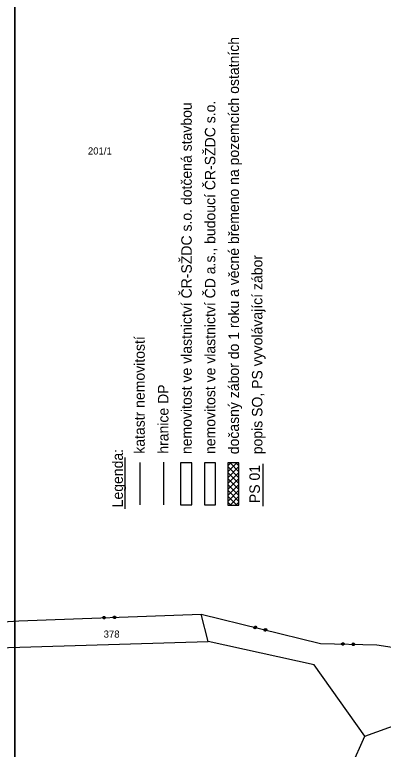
# Model space of a CAD drawing. Extents: x -866656 to -858817, y -1041816 to -1038653.
# Drawn here: x -864286.2 to -864198.3, y -1040985.3 to -1040809.9 of the extents above; entities that cross this region are included whole.
import ezdxf

# ---------------------------------------------------------------- set-up
doc = ezdxf.new("R2010")
doc.units = 0
for name, color, linetype in [('tisk ramy', 7, 'Continuous'), ('Vrstva 1', 7, 'Continuous'), ('Vrstva 3', 7, 'Continuous'), ('Vrstva 53', 7, 'Continuous'), ('Vrstva 7', 7, 'Continuous')]:
    doc.layers.add(name, color=color, linetype=linetype)

msp = doc.modelspace()

# ---------------------------------------------------------------- linework, layer by layer
at = {"layer": 'tisk ramy'}
for points in [[(-864009.22, -1041281.26), (-864009.22, -1040246.26), (-864286.22, -1040246.26), (-864286.22, -1041281.26)], [(-864286.22, -1041281.26), (-864286.22, -1040246.26), (-864009.22, -1040246.26), (-864009.22, -1041281.26)]]:
    msp.add_lwpolyline(points, close=True, dxfattribs=at)
at = {"layer": 'Vrstva 1'}
for p, q in [((-864240.08, -1040959.55), (-864241.77, -1040953.03)), ((-864315.22, -1040961.89), (-864240.08, -1040959.55)), ((-864214.8, -1040965.14), (-864240.08, -1040959.55)), ((-864202.71, -1040982.19), (-864142.49, -1040960.45)), ((-864202.71, -1040982.19), (-864214.8, -1040965.14)), ((-864221.29, -1041022.99), (-864202.71, -1040982.19))]:
    msp.add_line(p, q, dxfattribs=at)
at = {"layer": 'Vrstva 3'}
for p, q in [((-864235.42, -1040919.07), (-864233.28, -1040916.94)), ((-864235.42, -1040917.65), (-864234.7, -1040916.94)), ((-864232.76, -1040920.48), (-864235.42, -1040917.82)), ((-864235.42, -1040920.48), (-864232.76, -1040917.82)), ((-864232.76, -1040919.07), (-864234.89, -1040916.94)), ((-864232.76, -1040917.65), (-864233.47, -1040916.94)), ((-864232.76, -1040921.9), (-864235.42, -1040919.24)), ((-864235.42, -1040921.9), (-864232.76, -1040919.24)), ((-864232.76, -1040923.31), (-864235.42, -1040920.65)), ((-864235.42, -1040923.31), (-864232.76, -1040920.65)), ((-864232.76, -1040924.72), (-864235.42, -1040922.07)), ((-864235.42, -1040924.72), (-864232.76, -1040922.07)), ((-864232.76, -1040926.14), (-864235.42, -1040923.48)), ((-864235.42, -1040926.14), (-864232.76, -1040923.48)), ((-864233.28, -1040927.03), (-864235.42, -1040924.89)), ((-864234.89, -1040927.03), (-864232.76, -1040924.89)), ((-864234.7, -1040927.03), (-864235.42, -1040926.31)), ((-864233.47, -1040927.03), (-864232.76, -1040926.31)), ((-864314.63, -1040956.27), (-864285.28, -1040954.67)), ((-864314.63, -1040956.27), (-864285.28, -1040954.67)), ((-864285.28, -1040954.67), (-864241.77, -1040953.03)), ((-864285.28, -1040954.67), (-864241.77, -1040953.03)), ((-864265.23, -1040953.81), (-864265.04, -1040953.61)), ((-864265.23, -1040953.81), (-864265.04, -1040953.61)), ((-864265.22, -1040954.01), (-864265.23, -1040953.81)), ((-864265.22, -1040954.01), (-864265.23, -1040953.81)), ((-864265.01, -1040954.21), (-864265.22, -1040954.01)), ((-864265.01, -1040954.21), (-864265.22, -1040954.01)), ((-864265.13, -1040953.81), (-864265.12, -1040954.01)), ((-864265.13, -1040953.81), (-864265.12, -1040954.01)), ((-864265.12, -1040954.01), (-864265.02, -1040954.11)), ((-864265.12, -1040954.01), (-864265.02, -1040954.11)), ((-864265.04, -1040953.61), (-864264.83, -1040953.6)), ((-864265.04, -1040953.61), (-864264.83, -1040953.6)), ((-864265.03, -1040953.71), (-864264.83, -1040953.7)), ((-864265.03, -1040953.71), (-864264.83, -1040953.7)), ((-864265.02, -1040954.11), (-864265.03, -1040953.71)), ((-864265.02, -1040954.11), (-864265.03, -1040953.71)), ((-864264.81, -1040954.2), (-864265.01, -1040954.21)), ((-864264.81, -1040954.2), (-864265.01, -1040954.21)), ((-864264.93, -1040953.7), (-864264.92, -1040954.1)), ((-864264.93, -1040953.7), (-864264.92, -1040954.1)), ((-864264.83, -1040953.6), (-864264.63, -1040953.79)), ((-864264.83, -1040953.6), (-864264.63, -1040953.79)), ((-864264.83, -1040953.7), (-864264.82, -1040954.1)), ((-864264.83, -1040953.7), (-864264.82, -1040954.1)), ((-864264.82, -1040954.1), (-864264.72, -1040953.99)), ((-864264.82, -1040954.1), (-864264.72, -1040953.99)), ((-864264.62, -1040953.99), (-864264.81, -1040954.2)), ((-864264.62, -1040953.99), (-864264.81, -1040954.2)), ((-864264.72, -1040953.99), (-864264.73, -1040953.8)), ((-864264.72, -1040953.99), (-864264.73, -1040953.8)), ((-864264.63, -1040953.79), (-864264.62, -1040953.99)), ((-864264.63, -1040953.79), (-864264.62, -1040953.99)), ((-864262.73, -1040953.72), (-864262.54, -1040953.51)), ((-864262.73, -1040953.72), (-864262.54, -1040953.51)), ((-864262.72, -1040953.92), (-864262.73, -1040953.72)), ((-864262.72, -1040953.92), (-864262.73, -1040953.72)), ((-864262.51, -1040954.11), (-864262.72, -1040953.92)), ((-864262.51, -1040954.11), (-864262.72, -1040953.92)), ((-864262.63, -1040953.72), (-864262.62, -1040953.92)), ((-864262.63, -1040953.72), (-864262.62, -1040953.92)), ((-864262.62, -1040953.92), (-864262.52, -1040954.01)), ((-864262.62, -1040953.92), (-864262.52, -1040954.01)), ((-864262.54, -1040953.51), (-864262.34, -1040953.51)), ((-864262.54, -1040953.51), (-864262.34, -1040953.51)), ((-864262.53, -1040953.61), (-864262.33, -1040953.6)), ((-864262.53, -1040953.61), (-864262.33, -1040953.6)), ((-864262.52, -1040954.01), (-864262.53, -1040953.61)), ((-864262.52, -1040954.01), (-864262.53, -1040953.61)), ((-864262.31, -1040954.1), (-864262.51, -1040954.11)), ((-864262.31, -1040954.1), (-864262.51, -1040954.11)), ((-864262.43, -1040953.61), (-864262.42, -1040954.01)), ((-864262.43, -1040953.61), (-864262.42, -1040954.01)), ((-864262.34, -1040953.51), (-864262.13, -1040953.7)), ((-864262.34, -1040953.51), (-864262.13, -1040953.7)), ((-864262.33, -1040953.6), (-864262.32, -1040954)), ((-864262.33, -1040953.6), (-864262.32, -1040954)), ((-864262.32, -1040954), (-864262.22, -1040953.9)), ((-864262.32, -1040954), (-864262.22, -1040953.9)), ((-864262.12, -1040953.9), (-864262.31, -1040954.1)), ((-864262.12, -1040953.9), (-864262.31, -1040954.1)), ((-864262.22, -1040953.9), (-864262.23, -1040953.7)), ((-864262.22, -1040953.9), (-864262.23, -1040953.7)), ((-864262.13, -1040953.7), (-864262.12, -1040953.9)), ((-864262.13, -1040953.7), (-864262.12, -1040953.9)), ((-864241.77, -1040953.03), (-864213.28, -1040960.07)), ((-864241.77, -1040953.03), (-864213.28, -1040960.07)), ((-864229.2, -1040956.24), (-864229.15, -1040956.05)), ((-864229.2, -1040956.24), (-864229.15, -1040956.05)), ((-864229.05, -1040956.48), (-864229.2, -1040956.24)), ((-864229.05, -1040956.48), (-864229.2, -1040956.24)), ((-864229.15, -1040956.05), (-864228.91, -1040955.9)), ((-864229.15, -1040956.05), (-864228.91, -1040955.9)), ((-864229.05, -1040956.07), (-864229.1, -1040956.26)), ((-864229.05, -1040956.07), (-864229.1, -1040956.26)), ((-864229.1, -1040956.26), (-864229.03, -1040956.38)), ((-864229.1, -1040956.26), (-864229.03, -1040956.38)), ((-864228.86, -1040956.53), (-864229.05, -1040956.48)), ((-864228.86, -1040956.53), (-864229.05, -1040956.48)), ((-864229.03, -1040956.38), (-864228.93, -1040956)), ((-864229.03, -1040956.38), (-864228.93, -1040956)), ((-864228.93, -1040956), (-864228.74, -1040956.04)), ((-864228.93, -1040956), (-864228.74, -1040956.04)), ((-864228.84, -1040956.02), (-864228.93, -1040956.41)), ((-864228.84, -1040956.02), (-864228.93, -1040956.41)), ((-864228.91, -1040955.9), (-864228.71, -1040955.95)), ((-864228.91, -1040955.9), (-864228.71, -1040955.95)), ((-864228.62, -1040956.38), (-864228.86, -1040956.53)), ((-864228.62, -1040956.38), (-864228.86, -1040956.53)), ((-864228.74, -1040956.04), (-864228.83, -1040956.43)), ((-864228.74, -1040956.04), (-864228.83, -1040956.43)), ((-864228.83, -1040956.43), (-864228.71, -1040956.36)), ((-864228.83, -1040956.43), (-864228.71, -1040956.36)), ((-864228.71, -1040955.95), (-864228.57, -1040956.19)), ((-864228.71, -1040955.95), (-864228.57, -1040956.19)), ((-864228.71, -1040956.36), (-864228.67, -1040956.17)), ((-864228.71, -1040956.36), (-864228.67, -1040956.17)), ((-864228.57, -1040956.19), (-864228.62, -1040956.38)), ((-864228.57, -1040956.19), (-864228.62, -1040956.38)), ((-864226.72, -1040956.64), (-864226.48, -1040956.5)), ((-864226.72, -1040956.64), (-864226.48, -1040956.5)), ((-864226.48, -1040956.5), (-864226.29, -1040956.55)), ((-864226.48, -1040956.5), (-864226.29, -1040956.55)), ((-864226.77, -1040956.84), (-864226.72, -1040956.64)), ((-864226.77, -1040956.84), (-864226.72, -1040956.64)), ((-864226.63, -1040957.08), (-864226.77, -1040956.84)), ((-864226.63, -1040957.08), (-864226.77, -1040956.84)), ((-864226.63, -1040956.67), (-864226.68, -1040956.86)), ((-864226.63, -1040956.67), (-864226.68, -1040956.86)), ((-864226.68, -1040956.86), (-864226.6, -1040956.98)), ((-864226.68, -1040956.86), (-864226.6, -1040956.98)), ((-864226.43, -1040957.13), (-864226.63, -1040957.08)), ((-864226.43, -1040957.13), (-864226.63, -1040957.08)), ((-864226.6, -1040956.98), (-864226.51, -1040956.59)), ((-864226.6, -1040956.98), (-864226.51, -1040956.59)), ((-864226.51, -1040956.59), (-864226.31, -1040956.64)), ((-864226.51, -1040956.59), (-864226.31, -1040956.64)), ((-864226.41, -1040956.62), (-864226.51, -1040957.01)), ((-864226.41, -1040956.62), (-864226.51, -1040957.01)), ((-864226.19, -1040956.98), (-864226.43, -1040957.13)), ((-864226.19, -1040956.98), (-864226.43, -1040957.13)), ((-864226.31, -1040956.64), (-864226.41, -1040957.03)), ((-864226.31, -1040956.64), (-864226.41, -1040957.03)), ((-864226.41, -1040957.03), (-864226.29, -1040956.96)), ((-864226.41, -1040957.03), (-864226.29, -1040956.96)), ((-864226.29, -1040956.55), (-864226.14, -1040956.79)), ((-864226.29, -1040956.55), (-864226.14, -1040956.79)), ((-864226.29, -1040956.96), (-864226.24, -1040956.76)), ((-864226.29, -1040956.96), (-864226.24, -1040956.76)), ((-864226.14, -1040956.79), (-864226.19, -1040956.98)), ((-864226.14, -1040956.79), (-864226.19, -1040956.98)), ((-864208.27, -1040960.08), (-864208.06, -1040959.89)), ((-864208.27, -1040960.08), (-864208.06, -1040959.89)), ((-864208.07, -1040960.39), (-864208.07, -1040959.99)), ((-864208.07, -1040959.99), (-864207.86, -1040959.99)), ((-864208.07, -1040960.39), (-864208.07, -1040959.99)), ((-864208.07, -1040959.99), (-864207.86, -1040959.99)), ((-864208.06, -1040959.89), (-864207.86, -1040959.89)), ((-864208.06, -1040959.89), (-864207.86, -1040959.89)), ((-864207.96, -1040959.99), (-864207.97, -1040960.39)), ((-864207.96, -1040959.99), (-864207.97, -1040960.39)), ((-864207.86, -1040959.99), (-864207.87, -1040960.39)), ((-864207.86, -1040959.99), (-864207.87, -1040960.39)), ((-864207.86, -1040959.89), (-864207.67, -1040960.09)), ((-864207.86, -1040959.89), (-864207.67, -1040960.09)), ((-864205.77, -1040960.14), (-864205.56, -1040959.94)), ((-864205.77, -1040960.14), (-864205.56, -1040959.94)), ((-864205.56, -1040959.94), (-864205.36, -1040959.95)), ((-864205.56, -1040959.94), (-864205.36, -1040959.95)), ((-864205.36, -1040959.95), (-864205.17, -1040960.15)), ((-864205.36, -1040959.95), (-864205.17, -1040960.15)), ((-864213.28, -1040960.07), (-864199.86, -1040960.37)), ((-864213.28, -1040960.07), (-864199.86, -1040960.37)), ((-864208.27, -1040960.28), (-864208.27, -1040960.08)), ((-864208.27, -1040960.28), (-864208.27, -1040960.08)), ((-864208.08, -1040960.49), (-864208.27, -1040960.28)), ((-864208.08, -1040960.49), (-864208.27, -1040960.28)), ((-864208.17, -1040960.08), (-864208.17, -1040960.28)), ((-864208.17, -1040960.08), (-864208.17, -1040960.28)), ((-864208.17, -1040960.28), (-864208.07, -1040960.39)), ((-864208.17, -1040960.28), (-864208.07, -1040960.39)), ((-864207.88, -1040960.49), (-864208.08, -1040960.49)), ((-864207.88, -1040960.49), (-864208.08, -1040960.49)), ((-864207.67, -1040960.3), (-864207.88, -1040960.49)), ((-864207.67, -1040960.3), (-864207.88, -1040960.49)), ((-864207.87, -1040960.39), (-864207.77, -1040960.29)), ((-864207.87, -1040960.39), (-864207.77, -1040960.29)), ((-864207.77, -1040960.29), (-864207.77, -1040960.09)), ((-864207.77, -1040960.29), (-864207.77, -1040960.09)), ((-864207.67, -1040960.09), (-864207.67, -1040960.3)), ((-864207.67, -1040960.09), (-864207.67, -1040960.3)), ((-864205.77, -1040960.34), (-864205.77, -1040960.14)), ((-864205.77, -1040960.34), (-864205.77, -1040960.14)), ((-864205.58, -1040960.54), (-864205.77, -1040960.34)), ((-864205.58, -1040960.54), (-864205.77, -1040960.34)), ((-864205.67, -1040960.14), (-864205.67, -1040960.34)), ((-864205.67, -1040960.14), (-864205.67, -1040960.34)), ((-864205.67, -1040960.34), (-864205.57, -1040960.44)), ((-864205.67, -1040960.34), (-864205.57, -1040960.44)), ((-864205.38, -1040960.55), (-864205.58, -1040960.54)), ((-864205.38, -1040960.55), (-864205.58, -1040960.54)), ((-864205.57, -1040960.44), (-864205.57, -1040960.04)), ((-864205.57, -1040960.04), (-864205.36, -1040960.05)), ((-864205.57, -1040960.44), (-864205.57, -1040960.04)), ((-864205.57, -1040960.04), (-864205.36, -1040960.05)), ((-864205.46, -1040960.04), (-864205.47, -1040960.44)), ((-864205.46, -1040960.04), (-864205.47, -1040960.44)), ((-864205.17, -1040960.35), (-864205.38, -1040960.55)), ((-864205.17, -1040960.35), (-864205.38, -1040960.55)), ((-864205.36, -1040960.05), (-864205.37, -1040960.45)), ((-864205.36, -1040960.05), (-864205.37, -1040960.45)), ((-864205.37, -1040960.45), (-864205.27, -1040960.35)), ((-864205.37, -1040960.45), (-864205.27, -1040960.35)), ((-864205.27, -1040960.35), (-864205.27, -1040960.15)), ((-864205.27, -1040960.35), (-864205.27, -1040960.15)), ((-864205.17, -1040960.15), (-864205.17, -1040960.35)), ((-864205.17, -1040960.15), (-864205.17, -1040960.35)), ((-864199.86, -1040960.37), (-864185.25, -1040962.67)), ((-864199.86, -1040960.37), (-864185.25, -1040962.67))]:
    msp.add_line(p, q, dxfattribs=at)
msp.add_lwpolyline([(-864235.42, -1040927.03), (-864232.76, -1040927.03), (-864232.76, -1040916.94), (-864235.42, -1040916.94)], close=True, dxfattribs=at)
at = {"layer": 'Vrstva 53'}
msp.add_line((-864250.67, -1040926.93), (-864250.67, -1040916.8), dxfattribs=at)
at = {"layer": 'Vrstva 7'}
for p, q in [((-864259.86, -1040927.89), (-864259.86, -1040915.65)), ((-864256.33, -1040926.94), (-864256.33, -1040916.81))]:
    msp.add_line(p, q, dxfattribs=at)
for points in [[(-864244.01, -1040926.99), (-864244.01, -1040916.9), (-864246.67, -1040916.9), (-864246.67, -1040926.99)], [(-864232.76, -1040927.03), (-864232.76, -1040916.94), (-864235.42, -1040916.94), (-864235.42, -1040927.03)]]:
    msp.add_lwpolyline(points, close=True, dxfattribs=at)
for points in [[(-864238.35, -1040926.98), (-864238.35, -1040916.89), (-864241.01, -1040916.89), (-864241.01, -1040926.98), (-864238.35, -1040926.98)], [(-864226.96, -1040927.27), (-864226.96, -1040917.14)]]:
    msp.add_lwpolyline(points, dxfattribs=at)

# ---------------------------------------------------------------- texts
at = {"layer": 'Vrstva 1'}
for s, p in [('201/1', (-864268.77, -1040843.33)), ('378', (-864265.02, -1040958.66))]:
    msp.add_text(s, height=1.7, dxfattribs=at).set_placement(p)
at = {"layer": 'Vrstva 7'}
for s, p in [('dočasný zábor do 1 roku a věcné břemeno na pozemcích ostatních', (-864232.75, -1040914.87)), ('nemovitost ve vlastnictví ČR-SŽDC s.o. dotčená stavbou', (-864244.01, -1040914.84)), ('nemovitost ve vlastnictví ČD a.s., budoucí ČR-SŽDC s.o.', (-864238.38, -1040914.82)), ('popis SO, PS vyvolávající zábor', (-864227.16, -1040914.88)), ('katastr nemovitostí', (-864255.22, -1040914.76)), ('hranice DP', (-864249.56, -1040914.75)), ('Legenda:', (-864260.43, -1040927.55)), ('PS 01', (-864227.77, -1040926.54))]:
    msp.add_text(s, height=2.5, rotation=90, dxfattribs=at).set_placement(p)

doc.saveas('drawing.dxf')
